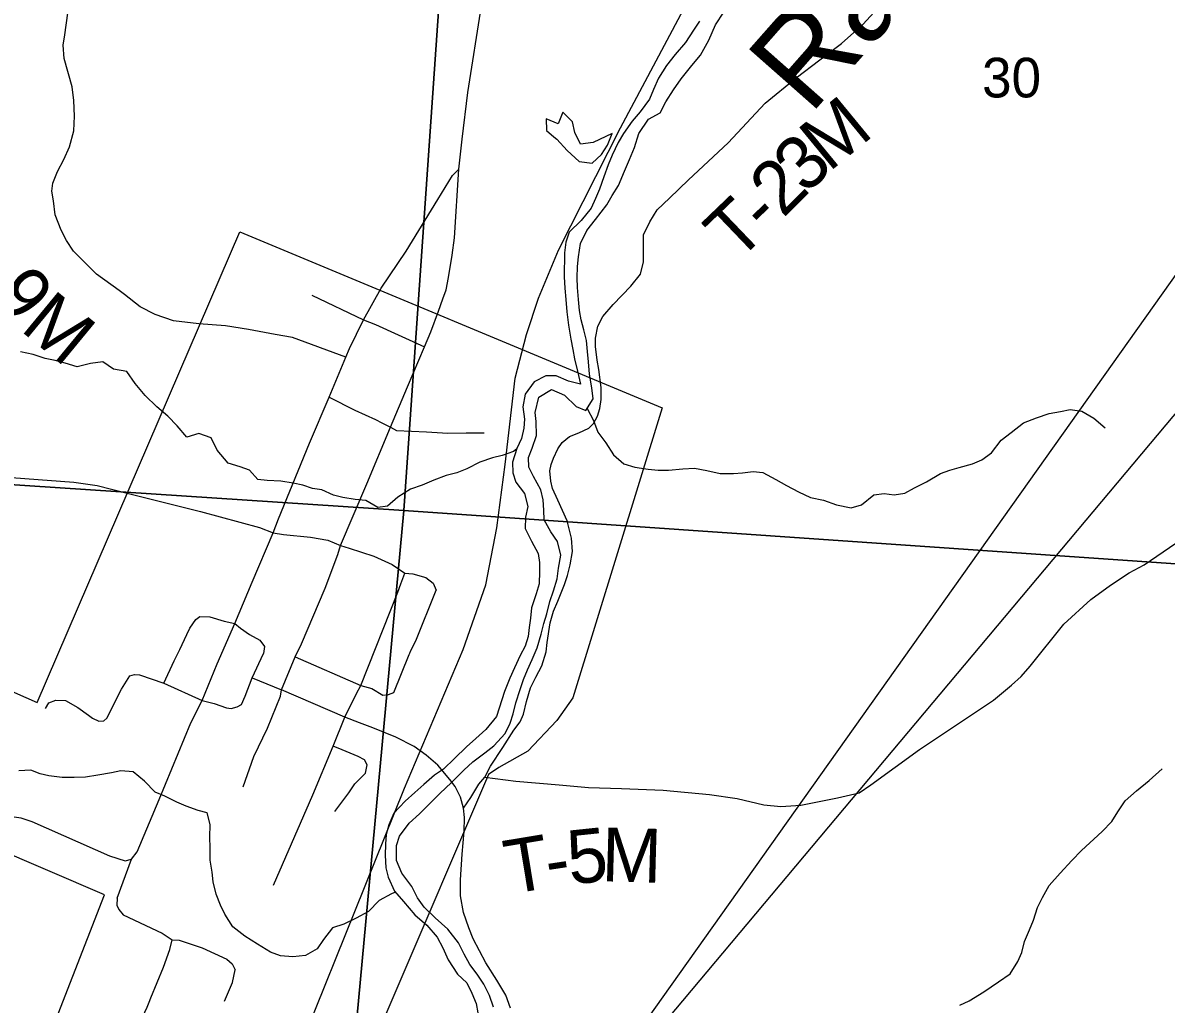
# Model space of a CAD drawing. Extents: x 0 to 34, y 0 to 22.
# Drawn here: x 5.937 to 7.144, y 17.363 to 18.398 of the extents above; entities that cross this region are included whole.
import ezdxf

# ---------------------------------------------------------------- set-up
doc = ezdxf.new("R2010")
doc.units = 0
for name, color, linetype in [('GM_X_City_Street', 7, 'Continuous'), ('GM_X_Corporation', 7, 'Continuous'), ('GM_X_Major_River', 7, 'Continuous'), ('GM_X_Major_River_Text', 7, 'Continuous'), ('GM_X_Minor_Lake', 7, 'Continuous'), ('GM_X_Minor_River', 7, 'Continuous'), ('GM_X_Rail_Line', 7, 'Continuous'), ('GM_X_Section', 7, 'Continuous'), ('GM_X_Section_Text', 7, 'Continuous'), ('GM_X_State_Route', 7, 'Continuous'), ('GM_X_Township_Road', 7, 'Continuous'), ('GM_X_Township_Road_Text', 7, 'Continuous'), ('SH_Text', 7, 'Continuous')]:
    doc.layers.add(name, color=color, linetype=linetype)

msp = doc.modelspace()

# ---------------------------------------------------------------- linework, layer by layer
at = {"layer": 'GM_X_City_Street'}
for p, q in [((6.1791, 17.707), (6.1908, 17.7328)), ((6.0366, 17.4746), (6.0517, 17.5157))]:
    msp.add_line(p, q, dxfattribs=at)
for points in [[(6.1263, 17.6832), (6.1419, 17.7219), (6.1608, 17.7645), (6.1789, 17.8081), (6.2012, 17.86), (6.2069, 17.8748), (6.2396, 17.9544), (6.2604, 18.003), (6.2779, 18.0453), (6.2818, 18.0545), (6.2964, 18.0845), (6.315, 18.118)], [(6.2418, 18.1106), (6.2964, 18.0845), (6.309, 18.0798), (6.3608, 18.0563)], [(6.2604, 18.003), (6.2872, 17.9893), (6.3093, 17.9794), (6.3158, 17.9761)], [(6.3158, 17.9761), (6.3251, 17.9713), (6.3313, 17.9678), (6.3631, 17.9665), (6.3854, 17.9651), (6.4047, 17.9653), (6.4144, 17.9655), (6.4238, 17.9653)], [(6.1243, 17.8825), (6.1866, 17.8657), (6.2012, 17.86), (6.2121, 17.8582), (6.2406, 17.8555), (6.2589, 17.8523), (6.2723, 17.8466), (6.2813, 17.8438), (6.3073, 17.8352), (6.3269, 17.8267), (6.34, 17.8173), (6.3487, 17.8166), (6.3623, 17.8129), (6.3702, 17.8069), (6.3732, 17.7995)], [(6.2014, 17.4884), (6.2431, 17.5836), (6.2644, 17.6349), (6.2768, 17.6656), (6.2892, 17.6904), (6.2937, 17.6988), (6.3326, 17.7975), (6.336, 17.8062), (6.34, 17.8173)], [(6.3454, 17.7332), (6.3466, 17.7358), (6.3517, 17.7462), (6.3732, 17.7995)], [(6.0857, 17.7013), (6.0968, 17.7251), (6.1025, 17.737), (6.1102, 17.7526), (6.1132, 17.7593), (6.1194, 17.7685)], [(6.1194, 17.7685), (6.1239, 17.7717), (6.1343, 17.7712), (6.1494, 17.7667), (6.1608, 17.7645), (6.1667, 17.7593), (6.1762, 17.7529), (6.1871, 17.7467), (6.192, 17.7402), (6.1908, 17.7328)], [(6.2245, 17.7291), (6.2937, 17.6988), (6.3053, 17.6956), (6.317, 17.6889), (6.3229, 17.6894), (6.3284, 17.6916)], [(6.3284, 17.6916), (6.3446, 17.7315), (6.3454, 17.7332)], [(5.9607, 17.6748), (5.9642, 17.6807), (5.9716, 17.6835), (5.9818, 17.683), (5.9949, 17.6758), (6.0063, 17.6678), (6.0106, 17.6644), (6.017, 17.6614), (6.0224, 17.6617), (6.0257, 17.6644), (6.0411, 17.6949), (6.05, 17.709), (6.0547, 17.7105), (6.0599, 17.7102), (6.0857, 17.7013), (6.1263, 17.6832)], [(6.1695, 17.5922), (6.1806, 17.6242), (6.195, 17.6541), (6.2089, 17.6877), (6.2101, 17.6944)], [(6.2664, 17.5662), (6.281, 17.5858), (6.2875, 17.5951), (6.2986, 17.6066), (6.3003, 17.6153), (6.2976, 17.6205), (6.2909, 17.6242), (6.2741, 17.6311), (6.2644, 17.6349)], [(6.0366, 17.4746), (6.0362, 17.4674), (6.0381, 17.4628), (6.0427, 17.4571), (6.0839, 17.4376), (6.0947, 17.4305)], [(6.022, 17.2152), (6.0252, 17.2494), (6.0273, 17.2604), (6.0326, 17.2748), (6.0396, 17.2917), (6.0438, 17.3016), (6.0512, 17.3236), (6.0681, 17.3597), (6.0704, 17.365), (6.0721, 17.3696), (6.0854, 17.4017), (6.0922, 17.4205), (6.0947, 17.4305)], [(6.0947, 17.4305), (6.1021, 17.4302), (6.1262, 17.4222), (6.1524, 17.4104), (6.1579, 17.4055), (6.161, 17.399)], [(6.1498, 17.366), (6.1583, 17.3855), (6.161, 17.399)]]:
    msp.add_lwpolyline(points, dxfattribs=at)
at = {"layer": 'GM_X_Corporation'}
msp.add_lwpolyline([(6.2264, 17.1339), (6.0126, 17.2209), (6.0141, 17.2532), (5.9678, 17.2531), (5.9382, 17.2604), (6.023, 17.4781), (5.8434, 17.5552), (5.9039, 17.7022), (5.952, 17.6811), (6.1661, 18.1773), (6.6117, 17.9917), (6.5173, 17.6859), (6.5005, 17.6619), (6.4701, 17.6297), (6.4392, 17.6123), (6.4283, 17.605)], close=True, dxfattribs=at)
at = {"layer": 'GM_X_Major_River'}
for points in [[(6.3854, 17.4419), (6.3722, 17.4537), (6.3606, 17.4652), (6.3534, 17.4751), (6.3474, 17.4869), (6.3369, 17.5011), (6.3313, 17.5144), (6.3314, 17.5303), (6.3345, 17.5401), (6.3448, 17.5537), (6.3555, 17.5635), (6.3674, 17.5756), (6.3769, 17.585), (6.3895, 17.5967), (6.4025, 17.6098), (6.412, 17.6185), (6.4246, 17.6279), (6.4341, 17.6354), (6.446, 17.6482), (6.4513, 17.6592), (6.4544, 17.669), (6.4572, 17.6808), (6.4618, 17.6948), (6.4653, 17.7054), (6.4695, 17.7156), (6.4746, 17.7265), (6.4799, 17.7387), (6.4842, 17.753), (6.4869, 17.7644), (6.49, 17.7746), (6.4932, 17.7875), (6.497, 17.7989), (6.5009, 17.8113), (6.5025, 17.8227), (6.5049, 17.8364), (6.5012, 17.8508), (6.4944, 17.8611), (6.4873, 17.8737), (6.487, 17.8839), (6.4863, 17.8949), (6.4837, 17.9052), (6.4758, 17.9193), (6.471, 17.9292), (6.4706, 17.9394), (6.4745, 17.9493), (6.4791, 17.9625), (6.4789, 17.9773), (6.4778, 17.9868), (6.4817, 18.0031), (6.495, 18.0113), (6.5086, 18.0052), (6.5211, 17.9933), (6.5313, 17.9891), (6.539, 18.0012), (6.5375, 18.0129), (6.535, 18.0274), (6.5339, 18.0403), (6.5328, 18.0513), (6.5318, 18.063), (6.5292, 18.0741), (6.5262, 18.0847), (6.5244, 18.0946), (6.5233, 18.106), (6.5223, 18.1189), (6.522, 18.1291), (6.5224, 18.1409), (6.5233, 18.1511), (6.5256, 18.1652), (6.5322, 18.1788), (6.5413, 18.1905), (6.5532, 18.2059), (6.559, 18.2158), (6.5658, 18.2263), (6.572, 18.2415), (6.5774, 18.2539), (6.5824, 18.2664), (6.5871, 18.2812), (6.5974, 18.2963), (6.6096, 18.303), (6.6157, 18.3144), (6.6238, 18.3272), (6.6318, 18.3389), (6.6429, 18.3529), (6.6521, 18.3638), (6.6609, 18.3797), (6.6679, 18.3959), (6.6767, 18.4091)], [(6.6512, 18.3998), (6.6447, 18.39), (6.6363, 18.3772), (6.6256, 18.3644), (6.6164, 18.353), (6.6079, 18.3395), (6.6026, 18.3277), (6.5983, 18.3175), (6.5884, 18.3039), (6.58, 18.2941), (6.5708, 18.2813), (6.5654, 18.2715), (6.5589, 18.2582), (6.5546, 18.248), (6.55, 18.2355), (6.5457, 18.2223), (6.5415, 18.2125), (6.5369, 18.2023), (6.5262, 18.1894), (6.5136, 18.177), (6.5101, 18.1664), (6.5085, 18.1554), (6.5083, 18.13), (6.509, 18.1182), (6.5101, 18.1061), (6.5111, 18.0932), (6.5129, 18.0791), (6.5155, 18.0643), (6.5173, 18.0533), (6.5191, 18.0434), (6.5225, 18.0305), (6.5254, 18.0168), (6.5129, 18.0199), (6.4997, 18.0257), (6.489, 18.0254), (6.4765, 18.0191), (6.4673, 18.0062), (6.4646, 17.993), (6.4664, 17.9797), (6.4659, 17.9702), (6.4632, 17.9596), (6.4582, 17.949), (6.4539, 17.9346), (6.4542, 17.9232), (6.4572, 17.9134), (6.4666, 17.9015), (6.4699, 17.8878), (6.4676, 17.8765), (6.4671, 17.8647), (6.4739, 17.851), (6.481, 17.8381), (6.4821, 17.8286), (6.4824, 17.8191), (6.4819, 17.8062), (6.4788, 17.7956), (6.4738, 17.7808), (6.4726, 17.7698), (6.4714, 17.76), (6.4702, 17.7505), (6.4671, 17.7403), (6.4617, 17.7304), (6.4559, 17.7176), (6.4509, 17.7066), (6.4455, 17.6926), (6.437, 17.6661), (6.4255, 17.6525), (6.4152, 17.6431), (6.4053, 17.6341), (6.3927, 17.6221), (6.3809, 17.6108), (6.3713, 17.6044), (6.3603, 17.5946), (6.3507, 17.5859), (6.3404, 17.5769), (6.3286, 17.5641), (6.3232, 17.552), (6.3205, 17.5418), (6.3196, 17.5315), (6.3192, 17.5198), (6.3202, 17.5065), (6.3225, 17.4966)], [(6.3225, 17.4966), (6.3292, 17.4821), (6.3386, 17.4711), (6.3506, 17.4569), (6.3635, 17.4462), (6.3744, 17.4336), (6.3804, 17.4222), (6.386, 17.4096), (6.3957, 17.3944), (6.4055, 17.3852), (6.4108, 17.3745), (6.4153, 17.3635), (6.4171, 17.3536)], [(6.4338, 17.3596), (6.4294, 17.3721), (6.4234, 17.3839), (6.4166, 17.3946), (6.4087, 17.4045), (6.4027, 17.4156), (6.3967, 17.4274), (6.3854, 17.4419)]]:
    msp.add_lwpolyline(points, dxfattribs=at)
at = {"layer": 'GM_X_Minor_Lake'}
for points in [[(6.5589, 18.281), (6.5389, 18.2715), (6.5256, 18.27), (6.5195, 18.2821), (6.5172, 18.2934), (6.507, 18.3037), (6.5021, 18.2915), (6.4892, 18.2968), (6.4896, 18.2843), (6.4975, 18.2778)], [(6.4975, 18.2778), (6.5006, 18.2752), (6.5113, 18.2631), (6.5242, 18.2518), (6.5378, 18.2499), (6.5476, 18.259), (6.554, 18.2689), (6.5589, 18.281)]]:
    msp.add_lwpolyline(points, dxfattribs=at)
at = {"layer": 'GM_X_Minor_River'}
for points in [[(6.4579, 17.9481), (6.4548, 17.9456), (6.443, 17.9414), (6.4328, 17.9391), (6.4192, 17.9345), (6.4056, 17.9276), (6.395, 17.9234), (6.3837, 17.9204), (6.3708, 17.9154), (6.3583, 17.9101), (6.3462, 17.9059), (6.3326, 17.8975), (6.3217, 17.888), (6.3115, 17.8868), (6.299, 17.894), (6.2876, 17.8951), (6.2747, 17.8974), (6.2649, 17.8996), (6.2524, 17.9053), (6.2425, 17.9068), (6.2323, 17.9101), (6.2221, 17.9124), (6.2092, 17.9146), (6.1948, 17.915), (6.185, 17.9161), (6.1762, 17.9259), (6.1664, 17.9297), (6.1535, 17.9335), (6.1421, 17.9471), (6.1356, 17.9603), (6.1227, 17.9649), (6.1102, 17.9607), (6.1, 17.9728), (6.0901, 17.983), (6.0783, 17.9928), (6.0662, 18.0049), (6.0555, 18.0174), (6.0468, 18.0303), (6.0328, 18.0325), (6.0214, 18.0404), (6.0082, 18.0385), (5.9942, 18.0351), (5.9817, 18.0388), (5.9711, 18.0418), (5.9604, 18.0437), (5.9479, 18.0479), (5.9343, 18.0509)], [(6.5325, 17.991), (6.5394, 17.9784), (6.544, 17.9663), (6.5524, 17.9549), (6.5604, 17.9424), (6.5714, 17.9326), (6.5828, 17.9292), (6.5968, 17.927), (6.6074, 17.9259), (6.6183, 17.9259), (6.6335, 17.9274), (6.646, 17.9282), (6.6589, 17.9256), (6.6729, 17.9226), (6.6869, 17.9226), (6.6967, 17.9234), (6.7077, 17.9246), (6.7179, 17.9235), (6.7316, 17.9163), (6.7429, 17.9099), (6.7558, 17.9031), (6.7683, 17.8974), (6.782, 17.8944), (6.7956, 17.8895), (6.8112, 17.8862), (6.8221, 17.8896), (6.8353, 17.8999), (6.8459, 17.9014), (6.8565, 17.8999), (6.8679, 17.9018), (6.8781, 17.9076), (6.8906, 17.9137), (6.9057, 17.9224), (6.9155, 17.9259), (6.9253, 17.9289), (6.9393, 17.9327), (6.9492, 17.9369), (6.9594, 17.9442), (6.9695, 17.9578), (6.9801, 17.9658), (6.9933, 17.9761), (7.0069, 17.9811), (7.0202, 17.986), (7.0323, 17.9879), (7.0425, 17.9899), (7.0546, 17.9884), (7.0675, 17.9808), (7.0793, 17.9706)], [(6.3303, 17.4808), (6.3261, 17.4792), (6.3132, 17.472), (6.3019, 17.4606), (6.2887, 17.4534), (6.2758, 17.4473), (6.2637, 17.4434), (6.2543, 17.4309), (6.2475, 17.421), (6.2354, 17.4142), (6.2218, 17.4126), (6.2089, 17.4137), (6.1983, 17.4175), (6.1847, 17.4262), (6.1714, 17.4345), (6.1585, 17.4443), (6.1501, 17.4576), (6.1455, 17.4674), (6.141, 17.4788), (6.1379, 17.4917), (6.1367, 17.5019), (6.1348, 17.5148), (6.1347, 17.5277), (6.1343, 17.5391), (6.1347, 17.5523), (6.1316, 17.5645), (6.1221, 17.5671), (6.1092, 17.5716), (6.0994, 17.5757), (6.0869, 17.5822), (6.0766, 17.5863), (6.0652, 17.598), (6.0535, 17.6079), (6.0402, 17.609), (6.0304, 17.6067), (6.016, 17.6044), (6.0031, 17.6024), (5.991, 17.602), (5.9785, 17.602), (5.9645, 17.6035), (5.9551, 17.6057), (5.9452, 17.6095), (5.9327, 17.6091)], [(6.926, 17.3616), (6.9359, 17.3662), (6.9514, 17.3757), (6.9668, 17.3864), (6.9789, 17.3947), (6.9872, 17.4077), (6.9914, 17.4172), (6.9943, 17.4289), (6.9996, 17.4411), (7.0037, 17.4513), (7.0079, 17.4646), (7.0131, 17.4752), (7.0203, 17.4881), (7.032, 17.5011), (7.044, 17.5144), (7.0542, 17.525), (7.0761, 17.5448), (7.0863, 17.5554), (7.0927, 17.5657), (7.1006, 17.5774), (7.1123, 17.5877), (7.1259, 17.5987), (7.1395, 17.6109)]]:
    msp.add_lwpolyline(points, dxfattribs=at)
at = {"layer": 'GM_X_Rail_Line'}
msp.add_lwpolyline([(5.1686, 16.7396), (5.2381, 16.7552), (5.4076, 16.7935), (5.6302, 16.838), (5.761, 16.8642), (5.834, 16.8816), (5.9075, 16.9106), (5.9775, 16.9517), (6.0279, 16.9921), (6.0831, 17.0404), (6.1385, 17.1164), (6.1838, 17.204), (6.3397, 17.5908), (6.4017, 17.7369), (6.4258, 17.8052), (6.4372, 17.8653), (6.4459, 17.9321), (6.4566, 18.0231), (6.4686, 18.0692), (6.4811, 18.1076), (6.5022, 18.1582), (6.5679, 18.2873), (6.8025, 18.728)], dxfattribs=at)
at = {"layer": 'GM_X_Section'}
for points in [[(5.4174, 18.9797), (6.4104, 18.9115), (6.3391, 17.8836), (5.3412, 17.9492)], [(6.4104, 18.9115), (7.3808, 18.8429), (7.3065, 17.8168), (6.3391, 17.8836)], [(5.3412, 17.9492), (6.3391, 17.8836), (6.2455, 16.872), (5.2673, 16.9365)], [(6.3391, 17.8836), (7.3065, 17.8168), (7.2305, 16.8022), (6.2455, 16.872)]]:
    msp.add_lwpolyline(points, close=True, dxfattribs=at)
at = {"layer": 'GM_X_State_Route'}
for points in [[(6.3755, 18.0936), (6.3804, 18.1068), (6.3836, 18.1163), (6.3861, 18.1294), (6.3901, 18.153), (6.3926, 18.171), (6.3973, 18.2437), (6.4005, 18.2752), (6.4067, 18.3245), (6.421, 18.416)], [(6.343, 18.0138), (6.3608, 18.0563), (6.3675, 18.0719), (6.3755, 18.0936)], [(6.2694, 17.8371), (6.2723, 17.8466), (6.3001, 17.9118), (6.3251, 17.9713), (6.343, 18.0138)], [(6.2101, 17.6944), (6.2245, 17.7291), (6.2309, 17.743), (6.2562, 17.8017), (6.2694, 17.8371)], [(5.9096, 17.5435), (5.9129, 17.5523), (5.9196, 17.5583), (5.9283, 17.5605), (5.9347, 17.5595), (5.9466, 17.5555), (6.0284, 17.5194), (6.0451, 17.5141), (6.0517, 17.5157), (6.0577, 17.5236), (6.081, 17.5786), (6.1142, 17.6594), (6.1263, 17.6832), (6.139, 17.68), (6.1519, 17.6753), (6.1568, 17.6748), (6.163, 17.6763), (6.1677, 17.679), (6.1717, 17.6877), (6.1791, 17.707), (6.2101, 17.6944)], [(6.3045, 17.6551), (6.3036, 17.6554), (6.2924, 17.6597), (6.2768, 17.6656), (6.2101, 17.6944)], [(6.4022, 17.5694), (6.3988, 17.5813), (6.3931, 17.5925), (6.3876, 17.5997), (6.375, 17.615), (6.3626, 17.6254), (6.3499, 17.6346), (6.3306, 17.6445), (6.3045, 17.6551)], [(6.4516, 17.3585), (6.4466, 17.3724), (6.4372, 17.388), (6.4255, 17.4063), (6.4124, 17.4318), (6.4077, 17.4435), (6.4022, 17.4596), (6.399, 17.477), (6.3988, 17.4941), (6.4007, 17.5211), (6.4027, 17.5449), (6.403, 17.5598), (6.4022, 17.5694)]]:
    msp.add_lwpolyline(points, dxfattribs=at)
at = {"layer": 'GM_X_Township_Road'}
for points in [[(6.4245, 17.6024), (6.4305, 17.6138), (6.4434, 17.6334), (6.4553, 17.6517), (6.4617, 17.6606), (6.4654, 17.6688), (6.4684, 17.682), (6.4729, 17.6963), (6.4783, 17.7077), (6.4848, 17.7196), (6.4892, 17.7345), (6.4905, 17.7442), (6.4935, 17.765), (6.4969, 17.7774), (6.5016, 17.7879), (6.5088, 17.8054), (6.512, 17.8151), (6.5148, 17.8262), (6.517, 17.8401), (6.516, 17.8545), (6.5113, 17.8726), (6.5016, 17.8944), (6.4959, 17.9068), (6.4942, 17.9145), (6.4932, 17.9254), (6.4947, 17.9321), (6.4969, 17.9388), (6.5016, 17.9484), (6.5061, 17.9551), (6.5141, 17.9615), (6.5239, 17.9655), (6.5344, 17.9705), (6.5393, 17.9752), (6.5435, 17.9829), (6.546, 17.9911), (6.5475, 18.0005), (6.5475, 18.0134), (6.5448, 18.0322), (6.543, 18.0422), (6.5415, 18.0565), (6.5415, 18.0652), (6.544, 18.0778), (6.5492, 18.088), (6.5599, 18.1007), (6.5785, 18.1202), (6.5889, 18.1329), (6.5919, 18.1458), (6.5919, 18.1624), (6.592, 18.1742), (6.5987, 18.1881), (6.6065, 18.2006), (6.6196, 18.2129), (6.6395, 18.2323), (6.6813, 18.2714), (6.7205, 18.3133), (6.7533, 18.3398), (6.778, 18.3588), (6.8009, 18.3762), (6.8235, 18.396), (6.8474, 18.4224)], [(5.9973, 18.15), (5.9904, 18.1569), (5.983, 18.1683), (5.9773, 18.1793), (5.9711, 18.1955), (5.9692, 18.2103), (5.9675, 18.2205), (5.9686, 18.2289), (5.9735, 18.2412), (5.9802, 18.2538), (5.9861, 18.2672), (5.9906, 18.2841), (5.9916, 18.2993), (5.9908, 18.3159), (5.9889, 18.3303), (5.9806, 18.3601), (5.9796, 18.3742), (5.9811, 18.3852), (5.9844, 18.408)], [(6.315, 18.118), (6.3415, 18.1569), (6.375, 18.2117), (6.3906, 18.237), (6.3973, 18.2437)], [(6.0444, 18.1112), (6.0385, 18.1157), (6.0147, 18.1328), (5.9973, 18.15)], [(6.2779, 18.0453), (6.2214, 18.0661), (6.2031, 18.0692), (6.175, 18.0745), (6.1507, 18.0783), (6.1226, 18.0804), (6.096, 18.0836), (6.0765, 18.0904), (6.0609, 18.0984), (6.0444, 18.1112)], [(5.7319, 17.931), (5.9011, 17.92), (5.9906, 17.9133), (6.0155, 17.91), (6.0472, 17.9019), (6.1243, 17.8825)], [(6.4022, 17.5694), (6.4097, 17.5808), (6.4183, 17.595), (6.4245, 17.6024), (6.4573, 17.5982), (6.5031, 17.594), (6.5341, 17.5915), (6.5688, 17.5902), (6.6129, 17.5885), (6.6618, 17.5838), (6.6908, 17.5798), (6.719, 17.5729), (6.7369, 17.5714), (6.7582, 17.5726), (6.7969, 17.5803), (6.8197, 17.5858), (6.832, 17.5942), (6.8834, 17.6314), (6.9613, 17.6836), (6.9806, 17.6993), (6.9907, 17.7085), (7.0001, 17.7192), (7.0356, 17.7638), (7.0641, 17.7898), (7.0849, 17.8049), (7.1047, 17.8176), (7.1205, 17.8261), (7.154, 17.8492)]]:
    msp.add_lwpolyline(points, dxfattribs=at)
at = {"layer": 'SH_Text'}
msp.add_lwpolyline([(6.4807, 17.185), (7.1921, 18.186), (7.3213, 18.186), (6.4807, 17.185)], close=True, dxfattribs=at)

# ---------------------------------------------------------------- texts
at = {"layer": 'GM_X_Major_River_Text'}
msp.add_text('Rac', height=0.0947, rotation=48.5724, dxfattribs=at).set_placement((6.7677, 18.2996))
at = {"layer": 'GM_X_Section_Text'}
msp.add_text('30', height=0.04186, rotation=0, dxfattribs=at).set_placement((6.9494, 18.3192))
at = {"layer": 'GM_X_Township_Road_Text'}
for s, rotation, p in [('M', 39.4168, (6.7877, 18.2398)), ('3', 45.0993, (6.7641, 18.216)), ('2', 45.1519, (6.7394, 18.1912)), ('T', 43.7726, (6.6909, 18.1445)), ('-', 44.0347, (6.7218, 18.1741)), ('9', 307.608, (5.9021, 18.1118)), ('M', 320.528, (5.9331, 18.0741)), ('5', 5.9747, (6.5145, 17.4889)), ('M', 358.4315, (6.5473, 17.4925)), ('T', 9.3848, (6.4504, 17.4786)), ('-', 8.5794, (6.4921, 17.4855))]:
    msp.add_text(s, height=0.0568, rotation=rotation, dxfattribs=at).set_placement(p)

doc.saveas('drawing.dxf')
